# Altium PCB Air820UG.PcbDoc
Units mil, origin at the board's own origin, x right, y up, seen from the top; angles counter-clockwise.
Board outline 6000 x 4000 mil, 2 copper layers (Top, Bottom), stack 12.7 mil thick; 1 components, 0 nets, 146 pads, 0 vias.
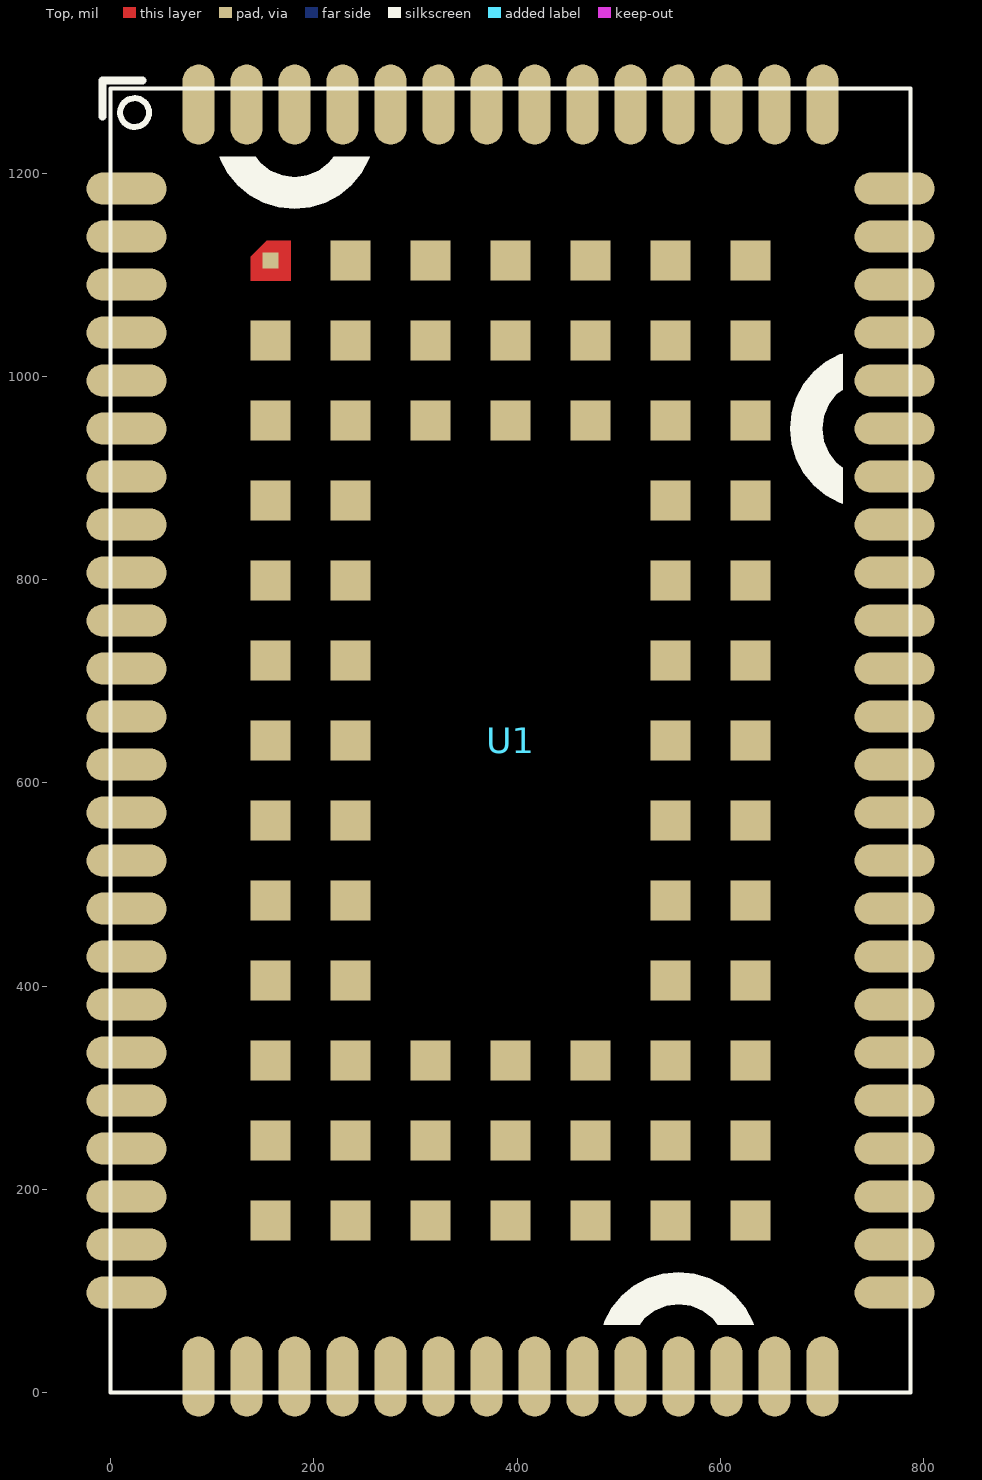
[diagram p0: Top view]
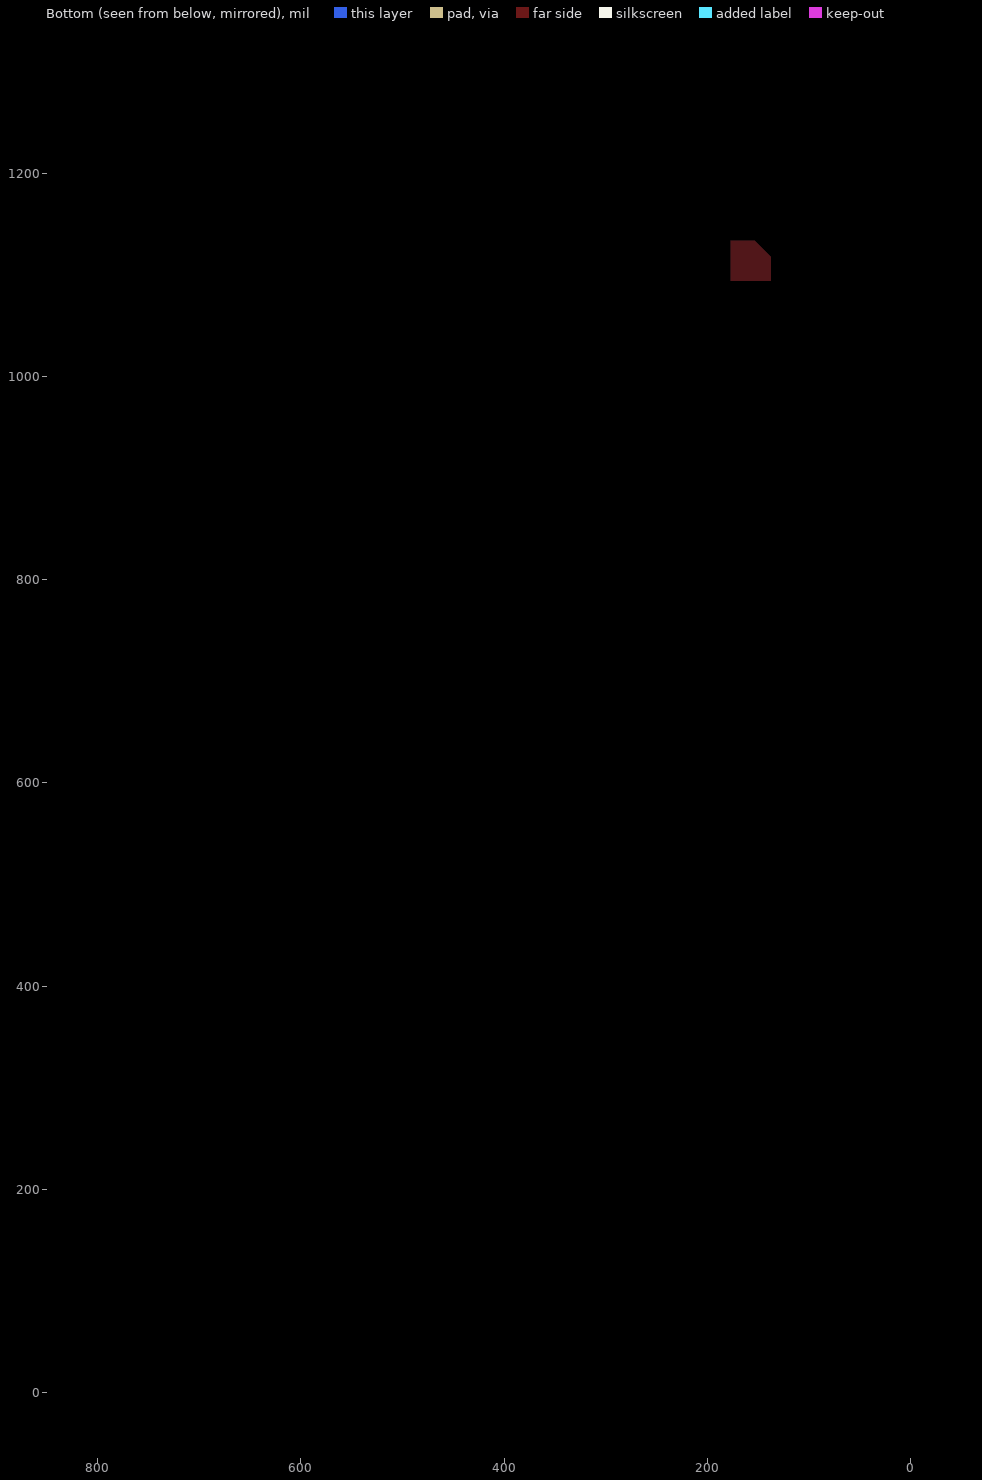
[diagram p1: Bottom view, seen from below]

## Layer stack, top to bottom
Solder Mask Top: solder mask 0.4, Solder Resist, Dk 3.5
Top: signal copper 1.35
Dielectric 1: dielectric 10, FR-4, Dk 4.3
Bottom: signal copper 1.35
Solder Mask Bottom: solder mask 0.4, Solder Resist, Dk 3.5

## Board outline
-9000,-9000 -3000,-9000 -3000,-5000 -9000,-5000

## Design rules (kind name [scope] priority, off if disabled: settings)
Clearance "Clearance - Default - DEFAULT- SMD" [IsVia vs IsSMTPin] p1: gap=6 ignorepadtopadclearanceinfootprint=FALSE
Clearance "Clearance - Default - DEFAULT - Via" [IsVia vs IsVia] p2: gap=6 ignorepadtopadclearanceinfootprint=FALSE
Clearance "Clearance - Default - DEFAULT - Net" [All] p3: gap=6 ignorepadtopadclearanceinfootprint=FALSE except(0: Arc-Hole Track-Hole SMDPad-Hole THPad-Hole Via-Hole Fill-Hole Poly-Hole Region-Hole Text-Hole; 10: Text-Text)
ComponentClearance "ComponentClearance - Default - DEFAULT" [All] p1: gap=6 collisioncheckmode=3 verticalgap=10 showdistances=FALSE
FanoutControl Fanout_Small [(CompPinCount < 5)] p3: bgadir=Out bgaviamode=Centered fanoutstyle=Auto fanoutdirection=OutThenIn viagrid=1 // Fanout_Small (Default Rule)
FanoutControl Fanout_SOIC [IsSOIC] p4: bgadir=Out bgaviamode=Centered fanoutstyle=Auto fanoutdirection=Alternating viagrid=1 // Fanout_SOIC (Default Rule)
HoleToHoleClearance "HoleToHoleClearance - Default - DEFAULT" [All] p1: gap=6 allowstackedmicrovias=TRUE
Length "Default Length" [All] p1: maxlimit=50000 minlimit=0 usedelayunits=FALSE
MaxMinImpedance "Default Impedance" [All] p1: minimum=50.00 maximum=150.0
ParallelSegment "Default Parallel Segment Adjasent" [All] p1: limit=1000 gap=200
ParallelSegment "Default Parallel Segment Same Layer" [All] p2: limit=1000 gap=200
PlaneConnect "Default PlaneConnect" [All] p1: planeconnectstyle=Relief reliefexpansion=20 reliefentries=4 reliefconductorwidth=15 reliefairgap=10
PolygonConnect "PolygonConnect - Default SMT" [IsSMTPin] p1: connectstyle=Relief reliefconductorwidth=10 reliefentries=4 polygonreliefangle="45 Angle" airgapwidth=10
PolygonConnect "PolygonConnect - Default Pad" [All] p2: connectstyle=Relief reliefconductorwidth=15 reliefentries=4 polygonreliefangle="45 Angle" airgapwidth=10
RoutingLayers "RoutingLayers - Default - DEFAULT" [All] p1: top layer_v5=TRUE bottom layer_v5=TRUE
RoutingPriority "RoutingPriority - Default - DEFAULT" [All] p1: routingpriority=3
RoutingTopology "Default Routing Topology" [All] p1: topology=Shortest
RoutingVias "RoutingVias - Default - DEFAULT" [All] p1: holewidth=37 width=55 viastyle="Through Hole" minholewidth=37 minwidth=55 maxholewidth=37 maxwidth=55
SMDToCorner "SMDToCorner - Default - DEFAULT" [All] p1: distance=60000
SolderMaskExpansion [All] p1: expansion=4
Width "Default Width" [All] p1: maxlimit=12 minlimit=12 preferedwidth=12
20 further rules are at their usual default settings.

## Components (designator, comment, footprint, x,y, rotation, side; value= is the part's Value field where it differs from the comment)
U1 "AIR820UG" AIR820UG 0,0 r0 top

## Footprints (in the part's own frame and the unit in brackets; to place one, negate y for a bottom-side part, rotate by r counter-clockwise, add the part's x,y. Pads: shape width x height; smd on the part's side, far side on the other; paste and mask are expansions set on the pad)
AIR820UG [mm]
  oval 2x0.8 smd: 1(0.4,30.1) 2(0.4,28.9) 3(0.4,27.7) 4(0.4,26.5) 5(0.4,25.3) 6(0.4,24.1) 7(0.4,22.9) 8(0.4,21.7) 9(0.4,20.5) 10(0.4,19.3) 11(0.4,18.1) 12(0.4,16.9) 13(0.4,15.7) 14(0.4,14.5) 15(0.4,13.3) 16(0.4,12.1) 17(0.4,10.9) 18(0.4,9.7) 19(0.4,8.5) 20(0.4,7.3) 21(0.4,6.1) 22(0.4,4.9) 23(0.4,3.7) 24(0.4,2.5) 39(19.6,2.5) 40(19.6,3.7) 41(19.6,4.9) 42(19.6,6.1) 43(19.6,7.3) 44(19.6,8.5) 45(19.6,9.7) 46(19.6,10.9) 47(19.6,12.1) 48(19.6,13.3) 49(19.6,14.5) 50(19.6,15.7) 51(19.6,16.9) 52(19.6,18.1) 53(19.6,19.3) 54(19.6,20.5) 55(19.6,21.7) 56(19.6,22.9) 57(19.6,24.1) 58(19.6,25.3) 59(19.6,26.5) 60(19.6,27.7) 61(19.6,28.9) 62(19.6,30.1)
  oval 0.8x2 smd: 25(2.2,0.4) 26(3.4,0.4) 27(4.6,0.4) 28(5.8,0.4) 29(7,0.4) 30(8.2,0.4) 31(9.4,0.4) 32(10.6,0.4) 33(11.8,0.4) 34(13,0.4) 35(14.2,0.4) 36(15.4,0.4) 37(16.6,0.4) 38(17.8,0.4) 63(17.8,32.2) 64(16.6,32.2) 65(15.4,32.2) 66(14.2,32.2) 67(13,32.2) 68(11.8,32.2) 69(10.6,32.2) 70(9.4,32.2) 71(8.2,32.2) 72(7,32.2) 73(5.8,32.2) 74(4.6,32.2) 75(3.4,32.2) 76(2.2,32.2)
  rect 0.4x0.4 smd: 77(4,28.3)
  rect 1x1 smd: 78(6,28.3) 79(8,28.3) 80(10,28.3) 81(12,28.3) 82(14,28.3) 83(16,28.3) 84(4,26.3) 85(6,26.3) 86(8,26.3) 87(10,26.3) 88(12,26.3) 89(14,26.3) 90(16,26.3) 91(4,24.3) 92(6,24.3) 93(8,24.3) 94(10,24.3) 95(12,24.3) 96(14,24.3) 97(16,24.3) 98(4,22.3) 99(6,22.3) 100(14,22.3) 101(16,22.3) 102(4,20.3) 103(6,20.3) 104(14,20.3) 105(16,20.3) 106(4,18.3) 107(6,18.3) 108(14,18.3) 109(16,18.3) 110(4,16.3) 111(6,16.3) 112(14,16.3) 113(16,16.3) 114(4,14.3) 115(6,14.3) 116(14,14.3) 117(16,14.3) 118(4,12.3) 119(6,12.3) 120(14,12.3) 121(16,12.3) 122(4,10.3) 123(6,10.3) 124(14,10.3) 125(16,10.3) 126(4,8.3) 127(6,8.3) 128(8,8.3) 129(10,8.3) 130(12,8.3) 131(14,8.3) 132(16,8.3) 133(4,6.3) 134(6,6.3) 135(8,6.3) 136(10,6.3) 137(12,6.3) 138(14,6.3) 139(16,6.3) 140(4,4.3) 141(6,4.3) 142(8,4.3) 143(10,4.3) 144(12,4.3) 145(14,4.3) 146(16,4.3)
  Top region: 3.5,27.8 4.5,27.8 4.5,28.8 3.9,28.8 3.5,28.4 3.5,27.8
  silkscreen extent -0.2,0 20,32.8

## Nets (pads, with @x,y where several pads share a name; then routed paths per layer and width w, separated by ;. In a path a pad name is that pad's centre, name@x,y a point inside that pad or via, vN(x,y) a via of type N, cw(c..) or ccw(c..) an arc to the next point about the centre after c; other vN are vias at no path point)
pads on no net: U1.1 U1.2 U1.3 U1.4 U1.5 U1.6 U1.7 U1.8 U1.9 U1.10 U1.11 U1.12 U1.13 U1.14 U1.15 U1.16 U1.17 U1.18 U1.19 U1.20 U1.21 U1.22 U1.23 U1.24 U1.25 U1.26 U1.27 U1.28 U1.29 U1.30 U1.31 U1.32 U1.33 U1.34 U1.35 U1.36 U1.37 U1.38 U1.39 U1.40 U1.41 U1.42 U1.43 U1.44 U1.45 U1.46 U1.47 U1.48 U1.49 U1.50 U1.51 U1.52 U1.53 U1.54 U1.55 U1.56 U1.57 U1.58 U1.59 U1.60 U1.61 U1.62 U1.63 U1.64 U1.65 U1.66 U1.67 U1.68 U1.69 U1.70 U1.71 U1.72 U1.73 U1.74 U1.75 U1.76 U1.77 U1.78 U1.79 U1.80 U1.81 U1.82 U1.83 U1.84 U1.85 U1.86 U1.87 U1.88 U1.89 U1.90 U1.91 U1.92 U1.93 U1.94 U1.95 U1.96 U1.97 U1.98 U1.99 U1.100 U1.101 U1.102 U1.103 U1.104 U1.105 U1.106 U1.107 U1.108 U1.109 U1.110 U1.111 U1.112 U1.113 U1.114 U1.115 U1.116 U1.117 U1.118 U1.119 U1.120 U1.121 U1.122 U1.123 U1.124 U1.125 U1.126 U1.127 U1.128 U1.129 U1.130 U1.131 U1.132 U1.133 U1.134 U1.135 U1.136 U1.137 U1.138 U1.139 U1.140 U1.141 U1.142 U1.143 U1.144 U1.145 U1.146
